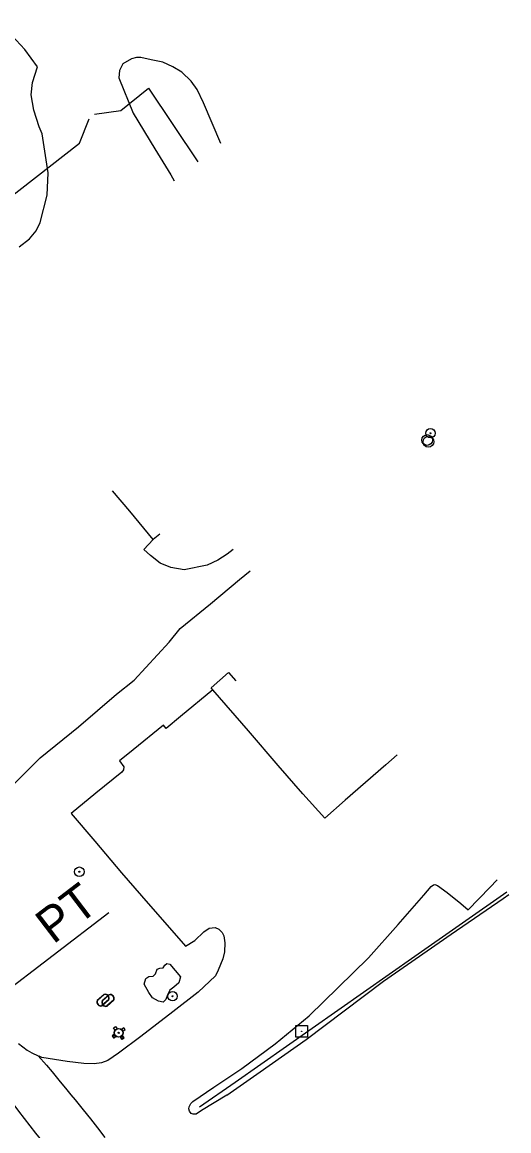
# Model space of a CAD drawing. Extents: x 471894 to 476235, y 503501 to 507878.
# Drawn here: x 473939 to 474163, y 505870 to 506379 of the extents above; entities that cross this region are included whole.
import ezdxf

# ---------------------------------------------------------------- set-up
doc = ezdxf.new("R2010")
doc.units = 0
for name, color, linetype in [('Exist Horizontal Alignment', 7, 'Continuous'), ('Exist Other Culture Area Outline', 7, 'Continuous'), ('Exist Other Culture Fence Line', 7, 'Continuous'), ('Exist Other Culture Gate', 7, 'Continuous'), ('Exist Other Culture Sign Post CELL', 7, 'Continuous'), ('Exist Roads EOP', 7, 'Continuous'), ('Exist Roads EOP Other', 7, 'Continuous'), ('Exist Utilities Other Located Object CELL', 7, 'Continuous'), ('Exist Utilities Other Pole CELL', 7, 'Continuous'), ('Exist Utilities Other Pole With Base CELL', 7, 'Continuous'), ('Exist Utilities Water Fire Hydrant CELL', 7, 'Continuous'), ('Exist Utilities Water Meter CELL', 7, 'Continuous')]:
    doc.layers.add(name, color=color, linetype=linetype)

msp = doc.modelspace()

# ---------------------------------------------------------------- linework, layer by layer
at = {"layer": 'Exist Horizontal Alignment'}
msp.add_line((473911.91, 505918.85), (473979.21, 505970.23), dxfattribs=at)
msp.add_arc((478558.54, 509466.62), 5849.93, 217.36226, 218.70549, dxfattribs=at)
at = {"layer": 'Exist Other Culture Area Outline'}
for points in [[(474002.6, 506143.76), (473999.59, 506141.24), (473988.76, 506154.28), (473980.93, 506163.64)], [(474026.9, 506072.33), (474026.09, 506073.32), (474034.05, 506080.3), (474037.52, 506076.45)], [(474007.19, 505946.54), (474012.13, 505940.75), (474011.25, 505938.01), (474009.04, 505936.04), (474007.24, 505934.67), (474006.11, 505932.57), (474005.3, 505930.43), (474004.18, 505929.19), (474002, 505929.57), (473999.28, 505931.07), (473997.5, 505933.6), (473995.46, 505937.46), (473996.23, 505939.98), (473997.56, 505940.96), (473999.46, 505941.04), (474000.57, 505942.13), (474001.42, 505944.3), (474002.65, 505944.72), (474004.09, 505944.96), (474004.93, 505946.18), (474005.79, 505946.87), (474007.19, 505946.54)]]:
    msp.add_lwpolyline(points, dxfattribs=at)
at = {"layer": 'Exist Other Culture Fence Line'}
for points in [[(473984.63, 506338.09), (473997.4, 506348.22), (474020.11, 506314.54)], [(473913.78, 506041.26), (473868.72, 506107.56), (473819.7, 506181.61), (473863.62, 506226.96), (473925.15, 506291.5), (473965.74, 506322.98)], [(474161.95, 505979.62), (474119.66, 505950.12), (474037.22, 505892.26), (474020.76, 505880.99)]]:
    msp.add_lwpolyline(points, dxfattribs=at)
at = {"layer": 'Exist Other Culture Gate'}
for p, q in [((473972.67, 506336.27), (473984.63, 506338.09)), ((473965.74, 506322.98), (473970.14, 506334.24))]:
    msp.add_line(p, q, dxfattribs=at)
at = {"layer": 'Exist Other Culture Sign Post CELL'}
for radius in [2.18, 0.24]:
    msp.add_circle((474008.43, 505931.88), radius, dxfattribs=at)
at = {"layer": 'Exist Roads EOP'}
msp.add_lwpolyline([(473937.65, 505910.24), (473941.72, 505907.16), (473943.87, 505905.89), (473946.71, 505904.48), (473950.59, 505900.21), (473953.18, 505897.21), (473956.3, 505893.39), (473959.83, 505889), (473961.71, 505886.7), (473963.67, 505884.33), (473967.44, 505879.74), (473970.76, 505875.61), (473973.95, 505871.54), (473977.33, 505867.11)], dxfattribs=at)
at = {"layer": 'Exist Roads EOP Other'}
for points in [[(473927.08, 506378.52), (473927.74, 506377.84), (473931.03, 506375.27), (473936.64, 506370.23), (473940.55, 506365.99)], [(473946.36, 506358.04), (473940.55, 506365.99)], [(474030.61, 506322.92), (474022.62, 506341.52), (474019.66, 506347.65), (474016.91, 506351.52), (474012.63, 506355.53), (474008.55, 506358.08), (474004.03, 506360.15), (473998.63, 506361.23), (473993.86, 506362.34), (473991.94, 506362.39), (473989.64, 506361.76), (473985.68, 506359.41), (473984.11, 506356.39), (473983.83, 506352.93), (473990.32, 506336.85), (474000.27, 506320.43), (474007.59, 506308.49), (474009.15, 506305.8)], [(473938.09, 506275.54), (473942.77, 506279.15), (473945.9, 506282.78), (473947.64, 506286.7), (473950.91, 506299.23), (473951.38, 506309.38), (473948.56, 506327.39), (473947.25, 506330.46), (473944.75, 506338.17), (473943.59, 506345.17), (473944.2, 506350.92), (473946.36, 506358.04)], [(474036.19, 506136.77), (474033.55, 506134.65), (474029.27, 506131.84), (474024.38, 506129.46), (474013.81, 506127.32), (474007.68, 506128.45), (474002.69, 506130.47), (473998.29, 506133.96), (473995.2, 506136.77), (473999.59, 506141.24)], [(473913.51, 505943.17), (473911.45, 505953.3), (473910.68, 505961.68), (473910.41, 505978.78), (473911.43, 505990.12), (473914.92, 506002.14), (473918.98, 506009.94), (473925.07, 506018.5), (473936, 506029.52), (473947.63, 506041.17), (473965.19, 506055.46), (473982.69, 506070.41), (473990.83, 506076.86), (474006.86, 506094.18), (474011.93, 506100.52), (474025.84, 506111.79), (474039.24, 506123), (474044.06, 506126.93)], [(474026.9, 506072.33), (474012.07, 506060.13), (474005.58, 506054.71), (474004.29, 506056.15), (473990.29, 506044.87), (473984.07, 506039.81), (473986.09, 506037.03), (473985.9, 506035.67), (473985.22, 506034.6), (473973.15, 506025.01), (473961.84, 506015.65), (473972.77, 506002.93), (473985.01, 505988.52), (473997.29, 505974.44), (474008.07, 505961.97), (474014.41, 505954.8), (474018.72, 505957.48), (474022.87, 505961.45), (474025.21, 505963.06), (474027.93, 505963.4), (474029.75, 505962.64), (474031.18, 505961.14), (474031.93, 505959.61), (474032.44, 505956.3), (474032.24, 505952.29), (474031.56, 505948.98), (474029.39, 505943.75), (474028.08, 505941.19), (474020.13, 505933.72), (474008.59, 505924.66), (473993.94, 505913.37), (473983.62, 505905.77), (473978.73, 505902.43), (473975.79, 505901.31), (473972.4, 505900.84), (473967.71, 505901.01), (473960.01, 505901.96), (473948.5, 505903.82), (473947.22, 505904.44)], [(474111.59, 506042.55), (474106.38, 506038.05), (474087.75, 506021.71), (474078.3, 506013.45), (474068.24, 506024.67), (474056.91, 506037.7), (474043.35, 506053.62), (474026.9, 506072.33)], [(474033.35, 505886.47), (474021.72, 505879.45), (474019.22, 505877.79), (474017.91, 505877.73), (474016.91, 505878.05), (474016.21, 505879.11), (474015.93, 505880.28), (474016.05, 505881.2), (474016.84, 505882.74), (474017.76, 505883.66), (474027.34, 505890.2), (474040.29, 505898.69), (474055.48, 505910.07), (474071.16, 505922.89), (474084.49, 505935.9), (474098.34, 505949.43), (474112.08, 505964.83), (474123.74, 505978.19), (474127.22, 505982.2), (474128.16, 505982.93), (474128.87, 505983.07), (474130.09, 505982.63), (474134.58, 505979.5), (474140.76, 505974.43), (474144.09, 505971.47), (474154.09, 505981.66), (474157.44, 505985.26)], [(474033.35, 505886.47), (474048.67, 505897.23), (474069.82, 505912.06), (474087.28, 505925.23), (474105.32, 505938.83), (474136.31, 505960.26), (474160.28, 505976.74), (474162.82, 505978.54)]]:
    msp.add_lwpolyline(points, dxfattribs=at)
at = {"layer": 'Exist Utilities Other Located Object CELL'}
for centre, radius in [((474126.84, 506190.04), 2.18), ((474126.84, 506190.04), 0.24), ((473965.65, 505988.96), 2.18), ((473965.65, 505988.96), 0.24)]:
    msp.add_circle(centre, radius, dxfattribs=at)
at = {"layer": 'Exist Utilities Other Pole CELL'}
for centre in [(474125.34, 506186.92), (474125.89, 506186.12)]:
    msp.add_circle(centre, 2.46, dxfattribs=at)
at = {"layer": 'Exist Utilities Other Pole With Base CELL'}
msp.add_line((474067.75, 505915.8), (474067.75, 505915.8), dxfattribs=at)
msp.add_lwpolyline([(474065.03, 505918.5), (474070.43, 505918.5), (474070.43, 505913.1), (474065.03, 505913.1), (474065.03, 505918.5)], dxfattribs=at)
msp.add_circle((474067.75, 505915.8), 0.0707, dxfattribs=at)
at = {"layer": 'Exist Utilities Water Fire Hydrant CELL'}
for p, q in [((473983.65, 505915.1), (473983.65, 505915.1)), ((473983.83, 505915.06), (473983.83, 505915.06))]:
    msp.add_line(p, q, dxfattribs=at)
for points in [[(473982.13, 505916.37), (473981.39, 505917.43), (473982.23, 505918.01), (473982.99, 505916.94)], [(473985.66, 505915.82), (473986.68, 505916.6), (473986.06, 505917.41), (473985.02, 505916.61)], [(473981.79, 505914.42), (473980.73, 505913.68), (473981.32, 505912.84), (473982.37, 505913.58)], [(473982.63, 505913.49), (473981.6, 505912.7), (473980.98, 505913.52), (473982.02, 505914.31)], [(473984.32, 505913.24), (473985.06, 505912.18), (473985.9, 505912.77), (473985.15, 505913.84)], [(473984.59, 505913.23), (473985.37, 505912.21), (473986.19, 505912.83), (473985.4, 505913.85)]]:
    msp.add_lwpolyline(points, dxfattribs=at)
for centre, radius in [((473983.65, 505915.1), 1.98), ((473983.83, 505915.06), 1.98), ((473983.65, 505915.1), 0.243), ((473983.83, 505915.06), 0.243)]:
    msp.add_circle(centre, radius, dxfattribs=at)
at = {"layer": 'Exist Utilities Water Meter CELL'}
for p, q in [((473976.52, 505930.08), (473976.52, 505930.08)), ((473978.82, 505929.93), (473978.82, 505929.93))]:
    msp.add_line(p, q, dxfattribs=at)
for points in [[(473973.87, 505930.02), (473976.94, 505932.7)], [(473973.96, 505929.92), (473977.03, 505932.6)], [(473979.08, 505930.24), (473975.99, 505927.55)], [(473979.17, 505930.14), (473976.08, 505927.44)], [(473976.17, 505929.84), (473979.21, 505932.55)], [(473976.26, 505929.74), (473979.3, 505932.45)], [(473981.38, 505930.12), (473978.32, 505927.39)], [(473981.48, 505930.02), (473978.42, 505927.29)]]:
    msp.add_lwpolyline(points, dxfattribs=at)
for centre, radius, start, end in [((473975.54, 505929.22), 1.86, 154.2381, 287.0395), ((473975.54, 505929.22), 1.73, 156.361, 284.8424), ((473977.85, 505929.05), 1.86, 154.9241, 287.7255), ((473977.49, 505930.93), 1.86, 334.7084, 107.3685), ((473977.5, 505930.94), 1.73, 336.1873, 105.9329), ((473979.79, 505930.79), 1.86, 335.3944, 108.0544), ((473979.8, 505930.8), 1.73, 336.8732, 106.6189), ((473977.86, 505929.06), 1.73, 157.047, 285.5284)]:
    msp.add_arc(centre, radius, start, end, dxfattribs=at)

# ---------------------------------------------------------------- texts
at = {"layer": 'Exist Horizontal Alignment'}
msp.add_text('PT', height=16, rotation=37.3623, dxfattribs=at).set_placement((473953.61, 505955.41))

doc.saveas('drawing.dxf')
